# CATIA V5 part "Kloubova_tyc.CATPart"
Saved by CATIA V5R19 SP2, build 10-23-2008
Part number: Kloubove tyce
Bounding box of the stored display mesh (mm): x -30 to 60, y -69.977 to 69.977, z -1000 to 1400
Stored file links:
  C:\Users\Martiin\Desktop\9.semestr\Projekt-diplomka\3D model\Kloubova_tyc.CATPart
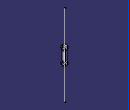
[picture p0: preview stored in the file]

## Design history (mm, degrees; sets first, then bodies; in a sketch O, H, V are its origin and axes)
Body1 (main body)
  Sketch1 on yz-plane, origin (0, 0, 0), H (0, 1, 0), V (0, 0, 1)
    circle A1 centre (0, 0) radius 40
    arc A2 centre (0, 0) radius 70 from (-50, 48.9898) to (50, 48.9898) ccw
    construction line L1 (-129.8975, 200) -> (180.7736, 200)
    point P3 (0, 400)
    arc A3 centre (0, 400) radius 70 from (-50, 351.0102) to (50, 351.0102) cw
    circle A4 centre (0, 400) radius 40
    line L2 (-50, 351.0102) -> (-50, 48.9898)
    construction line L3 (0, 400) -> (0, 103.5528)
    line L4 (50, 351.0102) -> (50, 48.9898)
    radius A1 = 40
    radius A2 = 70
    distance P3 L1 = 200
    distance P3 L2 = 50
    horizontal: L1 H
    symmetry: A2 A3 L1, A1 A4 L1, L2 L4 L3
    vertical: L2 V, L3 V
  Pad1: profile Sketch1, direction (1, 0, 0), length 40
  Sketch2 on end face of Pad1, origin (40, 0, 0), H (0, 1, 0), V (0, 0, 1)
    circle A1 centre (0, 0) radius 40
    reference projected circle E1 centre (0, 0) radius 40 from edge [end face of Pad1 | face of Pad1 from Sketch1.A1]
    circle A2 centre (0, 0) radius 65
    radius A2 = 65
    coincidence: A1 E1
  Pad2: profile Sketch2, direction (1, 0, 0), length 20
  RectPattern1: of Pad2, direction 1 instances 2, spacing 400, along edge [face of Pad1 from Sketch1.L4 | end face of Pad1]
  Plane1: type Offset, RefPlane end face of Pad1, Offset 25
  Mirror1: of the body so far, about Plane1
  DatumSurface1
  Point1: (0, 0, 400)
  Point2: (0, 0, 0)
  Line1: type PtPt, FirstPoint Point1, SecondPoint Point2, Start 1000, End 1000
